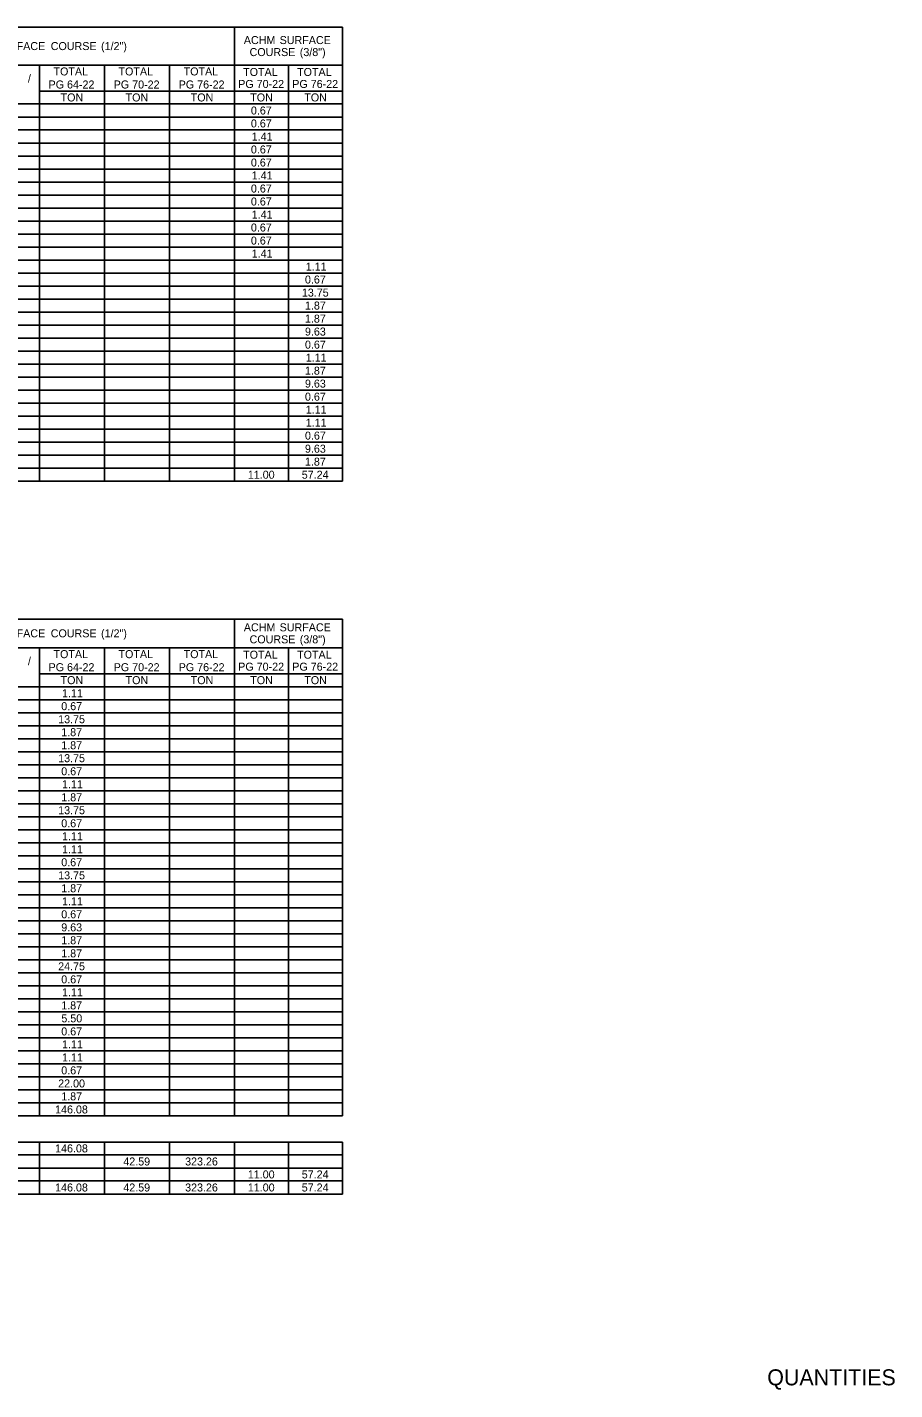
# Model space of a CAD drawing. Extents: x 540541 to 1930787, y -1948574 to 596640.
# Drawn here: x 560324 to 560974, y -1947044 to -1946023 of the extents above; entities that cross this region are included whole.
import ezdxf

# ---------------------------------------------------------------- set-up
doc = ezdxf.new("R2010")
doc.units = 0
doc.layers.add('Default', color=7, linetype='Continuous')
doc.layers.add('R_Border', color=7, linetype='Continuous')

msp = doc.modelspace()

# ---------------------------------------------------------------- linework, layer by layer
at = {"layer": 'Default'}
for p, q in [((559673.3, -1946022.7), (560560.1, -1946022.7)), ((560479.2, -1946363), (560479.2, -1946022.7)), ((560560.1, -1946363), (560560.1, -1946022.7)), ((560091.1, -1946051), (560560.1, -1946051)), ((560332.9, -1946363), (560332.9, -1946051)), ((560381.7, -1946363), (560381.7, -1946051)), ((560430.4, -1946363), (560430.4, -1946051)), ((560519.6, -1946363), (560519.6, -1946051)), ((560332.9, -1946070.5), (560430.4, -1946070.5)), ((560430.4, -1946070.5), (560560.1, -1946070.5)), ((560242.7, -1946080.2), (560560.1, -1946080.2)), ((560381.7, -1946363), (560381.7, -1946080.2)), ((560430.4, -1946363), (560430.4, -1946080.2)), ((559894.7, -1946090), (560560.1, -1946090)), ((559894.7, -1946099.7), (560560.1, -1946099.7)), ((559844.9, -1946109.5), (560560.1, -1946109.5)), ((559894.7, -1946119.2), (560560.1, -1946119.2)), ((559894.7, -1946129), (560560.1, -1946129)), ((559844.9, -1946138.7), (560560.1, -1946138.7)), ((559894.7, -1946148.5), (560560.1, -1946148.5)), ((559894.7, -1946158.2), (560560.1, -1946158.2)), ((559844.9, -1946168), (560560.1, -1946168)), ((559894.7, -1946177.7), (560560.1, -1946177.7)), ((559894.7, -1946187.5), (560560.1, -1946187.5)), ((559673.3, -1946197.2), (560479.2, -1946197.2)), ((559894.7, -1946197.2), (560332.9, -1946197.2)), ((560332.9, -1946197.2), (560560.1, -1946197.2)), ((559894.7, -1946207), (560560.1, -1946207)), ((559894.7, -1946216.7), (560560.1, -1946216.7)), ((559894.7, -1946226.5), (560560.1, -1946226.5)), ((559844.9, -1946236.2), (560560.1, -1946236.2)), ((559894.7, -1946246), (560560.1, -1946246)), ((559894.7, -1946255.7), (560560.1, -1946255.7)), ((559894.7, -1946265.5), (560560.1, -1946265.5)), ((559844.9, -1946275.2), (560560.1, -1946275.2)), ((559894.7, -1946285), (560560.1, -1946285)), ((559894.7, -1946294.7), (560560.1, -1946294.7)), ((559894.7, -1946304.5), (560560.1, -1946304.5)), ((560193, -1946314.2), (560560.1, -1946314.2)), ((559894.7, -1946324), (560560.1, -1946324)), ((560193, -1946333.7), (560560.1, -1946333.7)), ((560193, -1946343.5), (560560.1, -1946343.5)), ((559673.3, -1946353.2), (560560.1, -1946353.2)), ((560332.9, -1946363), (560332.9, -1946353.2)), ((560479.2, -1946353.2), (560560.1, -1946353.2)), ((559894.7, -1946363), (560560.1, -1946363)), ((559673.3, -1946466.3), (560560.1, -1946466.3)), ((560479.2, -1946838.8), (560479.2, -1946466.3)), ((560560.1, -1946838.8), (560560.1, -1946466.3)), ((560091.1, -1946487.8), (560560.1, -1946487.8)), ((560332.9, -1946838.8), (560332.9, -1946487.8)), ((560381.7, -1946838.8), (560381.7, -1946487.8)), ((560430.4, -1946838.8), (560430.4, -1946487.8)), ((560519.6, -1946838.8), (560519.6, -1946487.8)), ((560332.9, -1946507.3), (560430.4, -1946507.3)), ((560430.4, -1946507.3), (560560.1, -1946507.3)), ((559673.3, -1946517), (560560.1, -1946517)), ((560242.7, -1946517), (560560.1, -1946517)), ((560381.7, -1946829), (560381.7, -1946517)), ((560430.4, -1946829), (560430.4, -1946517)), ((559894.7, -1946526.8), (560560.1, -1946526.8)), ((559894.7, -1946536.5), (560560.1, -1946536.5)), ((559894.7, -1946546.3), (560560.1, -1946546.3)), ((559844.9, -1946556), (560560.1, -1946556)), ((559894.7, -1946565.8), (560560.1, -1946565.8)), ((559894.7, -1946575.5), (560560.1, -1946575.5)), ((559894.7, -1946585.3), (560560.1, -1946585.3)), ((559844.9, -1946595), (560560.1, -1946595)), ((559894.7, -1946604.8), (560560.1, -1946604.8)), ((559894.7, -1946614.5), (560560.1, -1946614.5)), ((559894.7, -1946624.3), (560560.1, -1946624.3)), ((559844.9, -1946634), (560560.1, -1946634)), ((559894.7, -1946643.8), (560560.1, -1946643.8)), ((559894.7, -1946653.5), (560560.1, -1946653.5)), ((559894.7, -1946663.3), (560560.1, -1946663.3)), ((559673.3, -1946673), (560560.1, -1946673)), ((559894.7, -1946682.8), (560560.1, -1946682.8)), ((559894.7, -1946692.5), (560560.1, -1946692.5)), ((559894.7, -1946702.3), (560560.1, -1946702.3)), ((559844.9, -1946712), (560560.1, -1946712)), ((559894.7, -1946721.8), (560560.1, -1946721.8)), ((559894.7, -1946731.5), (560560.1, -1946731.5)), ((559894.7, -1946741.3), (560560.1, -1946741.3)), ((559844.9, -1946751), (560560.1, -1946751)), ((559894.7, -1946760.8), (560560.1, -1946760.8)), ((559894.7, -1946770.5), (560560.1, -1946770.5)), ((559894.7, -1946780.3), (560560.1, -1946780.3)), ((559844.9, -1946790), (560560.1, -1946790)), ((559894.7, -1946799.8), (560560.1, -1946799.8)), ((559894.7, -1946809.5), (560560.1, -1946809.5)), ((559894.7, -1946819.3), (560560.1, -1946819.3)), ((559673.3, -1946829), (560560.1, -1946829)), ((560332.9, -1946838.8), (560332.9, -1946829)), ((559894.7, -1946838.8), (560560.1, -1946838.8)), ((559894.7, -1946858.3), (560560.1, -1946858.3)), ((559894.7, -1946858.3), (560560.1, -1946858.3)), ((560332.9, -1946887.5), (560332.9, -1946858.3)), ((560332.9, -1946897.3), (560332.9, -1946858.3)), ((560381.7, -1946897.3), (560381.7, -1946858.3)), ((560430.4, -1946897.3), (560430.4, -1946858.3)), ((560479.2, -1946897.3), (560479.2, -1946858.3)), ((560519.6, -1946897.3), (560519.6, -1946858.3)), ((560560.1, -1946897.3), (560560.1, -1946858.3)), ((559894.7, -1946868), (560560.1, -1946868)), ((559894.7, -1946877.8), (560560.1, -1946877.8)), ((559894.7, -1946887.5), (560560.1, -1946887.5)), ((559894.7, -1946897.3), (560560.1, -1946897.3))]:
    msp.add_line(p, q, dxfattribs=at)

# ---------------------------------------------------------------- texts
for s, p in [('ACHM', (560486.1, -1946035.3)), (' SURFACE', (560510.7, -1946035.3)), (' SURFACE', (560296.7, -1946039.8)), (' COURSE', (560339.2, -1946039.8)), (' (1/2")', (560376.9, -1946039.8)), ('COURSE', (560490.4, -1946044.3)), (' (3/8")', (560525.8, -1946044.3)), (' /', (560322.1, -1946064.1)), ('TOTAL', (560343.5, -1946058.8)), ('TOTAL', (560392.2, -1946058.8)), ('TOTAL', (560441, -1946058.8)), ('TOTAL', (560485.6, -1946059.2)), ('TOTAL', (560526, -1946059.2)), ('PG', (560339.8, -1946068.6)), (' 64-22', (560351.4, -1946068.6)), ('PG', (560388.6, -1946068.6)), (' 70-22', (560400.2, -1946068.6)), ('PG', (560437.3, -1946068.6)), (' 76-22', (560448.9, -1946068.6)), ('PG', (560481.9, -1946068.2)), (' 70-22', (560493.5, -1946068.2)), ('PG', (560522.4, -1946068.2)), (' 76-22', (560534, -1946068.2)), ('TON', (560348.8, -1946078.3)), ('TON', (560397.5, -1946078.3)), ('TON', (560446.3, -1946078.3)), ('TON', (560490.9, -1946078.3)), ('TON', (560531.4, -1946078.3)), ('0.67', (560491.4, -1946088.1)), ('0.67', (560491.4, -1946097.8)), ('0.67', (560491.4, -1946117.3)), ('1.41', (560492, -1946107.6)), ('0.67', (560491.4, -1946127.1)), ('1.41', (560492, -1946136.8)), ('0.67', (560491.4, -1946146.6)), ('0.67', (560491.4, -1946156.3)), ('1.41', (560492, -1946166.1)), ('0.67', (560491.4, -1946175.8)), ('0.67', (560491.4, -1946185.6)), ('1.41', (560492, -1946195.3)), ('1.11', (560532.5, -1946205.1)), ('0.67', (560531.9, -1946214.8)), ('13.75', (560529.6, -1946224.6)), ('1.87', (560531.9, -1946234.3)), ('1.87', (560531.9, -1946244.1)), ('9.63', (560531.9, -1946253.8)), ('0.67', (560531.9, -1946263.6)), ('1.11', (560532.5, -1946273.3)), ('1.87', (560531.9, -1946283.1)), ('9.63', (560531.9, -1946292.8)), ('0.67', (560531.9, -1946302.6)), ('1.11', (560532.5, -1946312.3)), ('0.67', (560531.9, -1946331.8)), ('1.11', (560532.5, -1946322.1)), ('9.63', (560531.9, -1946341.6)), ('1.87', (560531.9, -1946351.3)), ('11.00', (560489.1, -1946361.1)), ('57.24', (560529.5, -1946361.1)), (' SURFACE', (560296.7, -1946480)), (' COURSE', (560339.2, -1946480)), (' (1/2")', (560376.9, -1946480)), ('ACHM', (560486.1, -1946475.5)), ('COURSE', (560490.4, -1946484.5)), (' SURFACE', (560510.7, -1946475.5)), (' (3/8")', (560525.8, -1946484.5)), ('TOTAL', (560343.5, -1946495.6)), ('TOTAL', (560392.2, -1946495.6)), ('TOTAL', (560441, -1946495.6)), (' /', (560322.1, -1946500.9)), ('PG', (560339.8, -1946505.4)), (' 64-22', (560351.4, -1946505.4)), ('PG', (560388.6, -1946505.4)), (' 70-22', (560400.2, -1946505.4)), ('PG', (560437.3, -1946505.4)), (' 76-22', (560448.9, -1946505.4)), ('PG', (560481.9, -1946505)), ('TOTAL', (560485.6, -1946496)), (' 70-22', (560493.5, -1946505)), ('PG', (560522.4, -1946505)), ('TOTAL', (560526, -1946496)), (' 76-22', (560534, -1946505)), ('TON', (560348.8, -1946515.1)), ('TON', (560397.5, -1946515.1)), ('TON', (560446.3, -1946515.1)), ('TON', (560490.9, -1946515.1)), ('TON', (560531.4, -1946515.1)), ('1.11', (560349.9, -1946524.9)), ('0.67', (560349.3, -1946534.6)), ('13.75', (560347, -1946544.4)), ('1.87', (560349.3, -1946554.1)), ('1.87', (560349.3, -1946563.9)), ('13.75', (560347, -1946573.6)), ('0.67', (560349.3, -1946583.4)), ('1.11', (560349.9, -1946593.1)), ('1.87', (560349.3, -1946602.9)), ('13.75', (560347, -1946612.6)), ('0.67', (560349.3, -1946622.4)), ('1.11', (560349.9, -1946632.1)), ('1.11', (560349.9, -1946641.9)), ('0.67', (560349.3, -1946651.6)), ('13.75', (560347, -1946661.4)), ('1.87', (560349.3, -1946671.1)), ('1.11', (560349.9, -1946680.9)), ('0.67', (560349.3, -1946690.6)), ('9.63', (560349.3, -1946700.4)), ('1.87', (560349.3, -1946710.1)), ('1.87', (560349.3, -1946719.9)), ('24.75', (560347, -1946729.6)), ('0.67', (560349.3, -1946739.4)), ('1.11', (560349.9, -1946749.1)), ('1.87', (560349.3, -1946758.9)), ('5.50', (560349.4, -1946768.6)), ('0.67', (560349.3, -1946778.4)), ('1.11', (560349.9, -1946788.1)), ('1.11', (560349.9, -1946797.9)), ('0.67', (560349.3, -1946807.6)), ('22.00', (560347, -1946817.4)), ('1.87', (560349.3, -1946827.1)), ('146.08', (560344.7, -1946836.9)), ('146.08', (560344.7, -1946866.1)), ('42.59', (560395.8, -1946875.9)), ('323.26', (560442.1, -1946875.9)), ('11.00', (560489.1, -1946885.6)), ('57.24', (560529.5, -1946885.6)), ('146.08', (560344.7, -1946895.4)), ('42.59', (560395.8, -1946895.4)), ('323.26', (560442.1, -1946895.4)), ('11.00', (560489.1, -1946895.4)), ('57.24', (560529.5, -1946895.4))]:
    msp.add_text(s, height=6, dxfattribs=at).set_placement(p)
at = {"layer": 'R_Border'}
msp.add_text('QUANTITIES', height=12, rotation=360, dxfattribs=at).set_placement((560878.3, -1947040.7))

doc.saveas('drawing.dxf')
